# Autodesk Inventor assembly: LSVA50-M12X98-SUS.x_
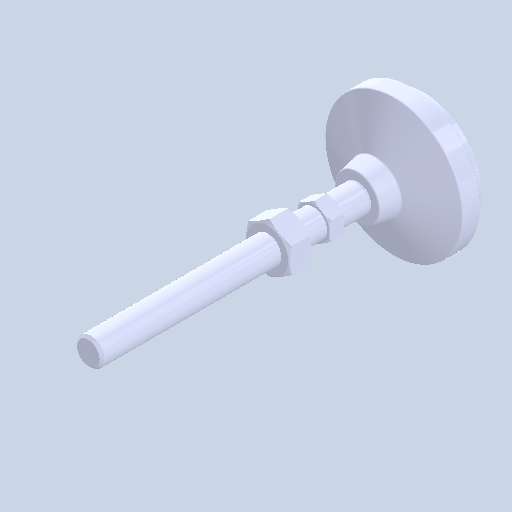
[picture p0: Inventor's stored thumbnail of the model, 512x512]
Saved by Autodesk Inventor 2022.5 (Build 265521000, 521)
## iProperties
Created: 2024-08
Part Number: LSVA50-M12X98-SUS.x_
Document SubType Name: Assembly
Designer: ImaoCorp
Author: ImaoCorp
Sending System: SOLIDWORKS 2022-2022290
MC: AMD64
MC_MODEL: Intel64 Family 6 Model 60 Stepping 3, GenuineIntel
OS: Windows_NT
FRU: Parasolid Version 33.1, build 260,  4-25-2022
FORMAT: text
GUISE: transmit
KEY: FILELSVA50-M12X98-SUS.x_t
DATE: Fri Aug 23 16:08:29 2024
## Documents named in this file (4)
- X:\14_SW2022-Inv2022\06_2024-10新製品(SME)\ELS_データ\l\lsva50-m12x98-sus\LSVA50-M12X98-SUS.x_.iam
- X:\14_SW2022-Inv2022\06_2024-10新製品(SME)\ELS_データ\l\lsva50-m12x98-sus\LSVA50-M12X98-SUS_01.ipt
- X:\14_SW2022-Inv2022\06_2024-10新製品(SME)\ELS_データ\l\lsva50-m12x98-sus\LSVA50-M12X98-SUS_02.ipt
- X:\14_SW2022-Inv2022\06_2024-10新製品(SME)\ELS_データ\l\lsva50-m12x98-sus\LSVA50-M12X98-SUS_03.ipt
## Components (3 placed, 3 different names)
1. LSVA50-M12X98-SUS_01
2. LSVA50-M12X98-SUS_02
3. LSVA50-M12X98-SUS_03
